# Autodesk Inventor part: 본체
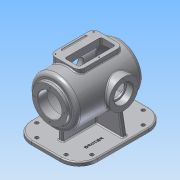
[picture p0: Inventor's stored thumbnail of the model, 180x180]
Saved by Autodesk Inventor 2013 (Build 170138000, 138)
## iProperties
Created: 2016-02
Part Number: 본체
Material: 알루미늄 6061
Document SubType Name: Modeling
Designer: mduedu
Density: 2.71 g/cm^3
Mass: 4129.67 g
Surface Area: 2907.55 cm^2
Volume: 1523.86 cm^3
Author: mduedu
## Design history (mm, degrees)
sketch "스케치2"
  geometry: L1 (0, 100)-(0, -100); L2 (65, -75.993)-(65, 100); L3 (65, 100)-(0, 100); A1 r 100 centre (0, 0) between (0, -100) and (65, -75.993); 2 further points
  constraints: 6 end point, 2 midpoint, 2 point on circle, 1 centre point, 1 coincident, 1 horizontal, 1 parallel, 1 vertical
  dimensions: "d3" = 200 distance of L1.start L1.end; "d5" = 130 diameter of L2 L1; "d6" = 100 radius of A1
revolve "회전1" sketch "스케치2" stored, may be unused: angle "d7" = 90 deg
sketch "스케치3"
  geometry: C1 r 47.5 at (0, 0); 1 further point
  constraints: 1 centre point, 1 coincident
  dimensions: "d8" = 95 diameter of C1
extrude "돌출2" join sketch "스케치3" distance "d10" = 10; taper "d11" = 0 deg
sketch "스케치5"
  geometry: L1 (47.5, 110)-(47.5, 100) reference; L2 (47.5, 100)-(65, 100) reference; L3 (65, 100)-(65, -75.993) reference; L4 (-65, -75.993)-(-65, 100) reference; L5 (-65, 100)-(-47.5, 100) reference; L6 (-47.5, 100)-(-47.5, 110) reference; L7 (-47.5, 110)-(47.5, 110) reference; L8 (55, 85)-(55, -71.239); L9 (0, 85)-(55, 85); L10 (0, 85)-(0, -90); A1 r 100 centre (0, 0) between (0, -100) and (65, -75.993) reference; A2 r 100 centre (0, 0) between (-65, -75.993) and (0, -100) reference; A3 r 90 centre (0, 0) between (0, -90) and (55, -71.239); 1 further point
  constraints: 6 end point, 2 point on circle, 1 centre point, 1 parallel, 1 perpendicular, 1 point on line, 1 vertical
  dimensions: "d13" = 10 distance between parallel lines of L3 L8; "d14" = 10 radial gap between concentric circles of A3 A1; "d15" = 15 distance between parallel lines of L9 L2
revolve "회전2" sketch "스케치5" stored, may be unused: angle "d16" = 90 deg
hole "구멍1" diameter "d19" = 65; stored, may be unused: countersink angle "d23" = 90 deg, drill point angle "d25" = 118 deg; dims "d17" = 10, "d18" = 10, "d20" = 6, "d21" = 4, "d22" = 2, "d24" = 8
node "작업 평면1"
sketch "스케치6"
  geometry: L1 (47.5, 110)-(-47.5, 110) reference; C1 r 40 at (0, -17); 1 further point
  constraints: 1 centre point, 1 vertical alignment
  dimensions: "d27" = 80 diameter of C1; "d29" = 127 distance from line of C1.centre L1
extrude "돌출3" join sketch "스케치6" stored distance "d30" = 10; taper "d31" = 0 deg
hole "구멍2" diameter "d34" = 42; stored, may be unused: countersink angle "d38" = 90 deg, drill point angle "d40" = 118 deg; dims "d32" = 10, "d33" = 10, "d35" = 6, "d36" = 52, "d37" = 18, "d39" = 8
sketch "스케치7" dims "d41" = 65
  geometry: C1 r 40 at (0, 0) reference; 3 further points
  constraints: 2 vertical alignment, 1 coincident, 2 other
hole "구멍3" sketch "스케치7" at (0, 32.5) diameter "d43" = 3.242; stored, may be unused: countersink angle "d47" = 90 deg, drill point angle "d49" = 118 deg; dims "d44" = 11, "d45" = 13, "d46" = 18, "d48" = 13
sketch "스케치8" dims "d53" = 80
  geometry: 3 further points
  constraints: 2 vertical alignment, 1 coincident, 2 other
hole "구멍4" sketch "스케치8" at (0, 40) diameter "d56" = 3.242; stored, may be unused: countersink angle "d60" = 90 deg, drill point angle "d62" = 118 deg; dims "d57" = 11, "d58" = 13, "d59" = 18, "d61" = 13
fillet "모깎기1" dims "d66" = 10
fillet "모깎기2" dims "d67" = 3
fillet "모깎기3" dims "d68" = 0.3
chamfer "모따기1" distance "d69" = 1; stored, may be unused: second distance "d70" = 2, angle "d71" = 45 deg
node "작업 평면5"
sketch "스케치23"
  geometry: L1 (6, 80)-(-6, 80); L2 (-6, 80)-(-6, -60); L3 (-6, -60)-(6, -60); L4 (6, -60)-(6, 80); L5 (-55, 100)-(55, 100) reference; 2 further points
  constraints: 8 end point, 2 parallel, 1 horizontal, 1 midpoint, 1 perpendicular, 1 vertical alignment
  dimensions: "d177" = 12 distance of L1.start L1.end; "d179" = 140 distance of L3.end L1.start; "d180" = 20 distance between parallel lines of L1 L5
extrude "돌출14" join sketch "스케치23" stored distance "d181" = 10; taper "d182" = 0 deg
node "작업 평면6"
sketch "스케치15"
  geometry: L1 (-30, 60)-(50, 60); L2 (50, 60)-(50, -60); L3 (50, -60)-(-30, -60); L4 (-30, -60)-(-30, 60); 3 further points
  constraints: 8 end point, 2 parallel, 1 horizontal, 1 horizontal alignment, 1 midpoint, 1 perpendicular, 1 vertical alignment
  dimensions: "d110" = 80 distance of L2.end L3.end; "d112" = 60 distance from line of L3 point (10, 0); "d113" = 120 distance of L1.end L2.end; "d149" = 30 distance from line of L4 point (0, 0)
extrude "돌출8" join sketch "스케치15" stored distance "d114" = 10; taper "d115" = 0 deg
fillet "모깎기7" dims "d116" = 15
sketch "스케치16"
  geometry: L1 (-30, -45)-(-30, 45) reference; L2 (-15, 60)-(35, 60) reference; L3 (35, -60)-(-15, -60) reference; L4 (-20, -45)-(-20, 45); L5 (-15, 50)-(15, 50); L6 (20, 45)-(20, -45); L7 (15, -50)-(-15, -50); L8 (50, 45)-(50, -45) reference; A1 r 15 centre (-15, -45) between (-30, -45) and (-15, -60) reference; A2 r 15 centre (-15, 45) between (-15, 60) and (-30, 45) reference; A3 r 5 centre (-15, -45) between (-20, -45) and (-15, -50); A4 r 5 centre (-15, 45) between (-15, 50) and (-20, 45); A5 r 5 centre (15, 45) between (20, 45) and (15, 50); A6 r 5 centre (15, -45) between (15, -50) and (20, -45); A7 r 15 centre (35, 45) between (50, 45) and (35, 60) reference; A8 r 15 centre (35, -45) between (35, -60) and (50, -45) reference
  constraints: 8 end point, 8 point on circle, 4 centre point, 2 equal radius, 3 other
  dimensions: "d137" = 10 distance between parallel lines of L4 L1; "d150" = 40 distance between parallel lines of L6 L4; "d151" = 100 distance between parallel lines of L7 L5
extrude "돌출9" cut sketch "스케치16" stored distance "d118" = 10; taper "d119" = 0 deg
fillet "모깎기8" dims "d120" = 3
sketch "스케치17"
  geometry: L1 (-30, -45)-(-30, 45) reference; L2 (-20, 45)-(-20, -45) reference; L3 (-15, -50)-(15, -50) reference; L4 (20, -45)-(20, 45) reference; L5 (15, 50)-(-15, 50) reference; L6 (-15, 60)-(35, 60) reference; L7 (35, -60)-(-15, -60) reference; L8 (15, 55)-(-15, 55); L9 (-25, 45)-(-25, -45); L10 (-15, -55)-(15, -55); L11 (25, -45)-(25, 45); L12 (50, 45)-(50, -45) reference; L13 (35, 55)-(-15, 55); L14 (-25, 45)-(-25, -45); L15 (-15, -55)-(35, -55); L16 (45, -45)-(45, 45); A1 r 5 centre (-15, 45) between (-15, 50) and (-20, 45) reference; A2 r 5 centre (-15, -45) between (-20, -45) and (-15, -50) reference; A3 r 5 centre (15, -45) between (15, -50) and (20, -45) reference; A4 r 5 centre (15, 45) between (20, 45) and (15, 50) reference; A5 r 15 centre (-15, 45) between (-15, 60) and (-30, 45) reference; A6 r 15 centre (-15, -45) between (-30, -45) and (-15, -60) reference; A7 r 10 centre (-15, 45) between (-15, 55) and (-25, 45); A8 r 10 centre (-15, -45) between (-25, -45) and (-15, -55); A9 r 10 centre (15, -45) between (15, -55) and (25, -45); A10 r 10 centre (15, 45) between (25, 45) and (15, 55); A11 r 15 centre (35, 45) between (50, 45) and (35, 60) reference; A12 r 15 centre (35, -45) between (35, -60) and (50, -45) reference; A13 r 10 centre (-15, 45) between (-15, 55) and (-25, 45); A14 r 10 centre (-15, -45) between (-25, -45) and (-15, -55); A15 r 10 centre (35, -45) between (35, -55) and (45, -45); A16 r 10 centre (35, 45) between (45, 45) and (35, 55); 6 further points
  constraints: 18 point on circle, 16 end point, 8 centre point, 4 midpoint, 4 tangent, 11 other
  dimensions: "d138" = 5 distance between parallel lines of L8 L6; "d157" = 5 distance between parallel lines of L12 L16
hole "구멍5" sketch "스케치17" at (-25, 0), (42.071, 52.071), (42.071, -52.071) diameter "d122" = 3.242; stored, may be unused: countersink angle "d126" = 90 deg, drill point angle "d128" = 118 deg; dims "d123" = 9, "d124" = 13, "d125" = 18, "d127" = 11
sketch "스케치19"
  geometry: L1 (-50, 70)-(-35, 70) reference; L2 (-50, 42.603)-(-50, 70) reference; C1 r 2.5 at (-43, 70); 1 further point
  constraints: 1 centre point, 1 point on line
  dimensions: "d152" = 5 diameter of C1; "d153" = 7 distance from line of C1.centre L2
extrude "돌출11" cut sketch "스케치19" stored distance "d154" = 70; taper "d155" = 0 deg
fillet "모깎기11" dims "d156" = 2.5
sketch "스케치20"
  geometry: L1 (-90, 120)-(90, 120); L2 (90, 120)-(90, -120); L3 (90, -120)-(-90, -120); L4 (-90, -120)-(-90, 120); 3 further points
  constraints: 8 end point, 2 parallel, 2 vertical alignment, 1 coincident, 1 horizontal, 1 midpoint, 1 perpendicular
  dimensions: "d162" = 180 distance of L1.start L1.end; "d164" = 240 distance of L1.end L2.end; "d165" = 120 distance from line of L1 point (0, 0)
extrude "돌출12" join sketch "스케치20" distance "d166" = 10; taper "d167" = 0 deg
fillet "모깎기12" dims "d168" = 50
node "작업 평면8"
  node "작업축1"
sketch "스케치24"
  geometry: L1 (128, 34.121)-(127.026, 32.5) reference; L2 (127.026, 32.5)-(128, 30.879) reference; L3 (128, 30.879)-(141, 30.879) reference; L4 (141, 30.879)-(141, 27) reference; L5 (141, 27)-(140, 26) reference; L6 (140, 26)-(123.3, 26) reference; L7 (123, 25.7)-(123, 21) reference; L8 (123, 21)-(116.833, 21) reference; L9 (86, 51.235)-(86, 70) reference; L10 (86, 70)-(106.5, 70) reference; L11 (111.5, 70)-(116, 70) reference; L12 (116, 70)-(116, 42.603) reference; L13 (118.678, 40)-(141, 40) reference; L14 (141, 40)-(141, 34.121) reference; L15 (141, 34.121)-(128, 34.121) reference; L16 (4, -34.121)-(4.974, -32.5) reference; L17 (4.974, -32.5)-(4, -30.879) reference; L18 (4, -30.879)-(-9, -30.879) reference; L19 (-9, -30.879)-(-9, -27) reference; L20 (-9, -27)-(-8, -26) reference; L21 (-8, -26)-(8.7, -26) reference; L22 (9, -25.7)-(9, -21) reference; L23 (9, -21)-(15.167, -21) reference; L24 (116.833, -21)-(123, -21) reference; L25 (123, -21)-(123, -25.7) reference; L26 (123.3, -26)-(140, -26) reference; L27 (140, -26)-(141, -27) reference; L28 (141, -27)-(141, -30.879) reference; L29 (141, -30.879)-(128, -30.879) reference; L30 (128, -30.879)-(127.026, -32.5) reference; L31 (127.026, -32.5)-(128, -34.121) reference; L32 (128, -34.121)-(141, -34.121) reference; L33 (141, -34.121)-(141, -40) reference; L34 (141, -40)-(118.678, -40) reference; L35 (72, -64.722)-(72, -100) reference; L36 (72, -100)-(156, -100) reference; L37 (156, -100)-(156, -110) reference; L38 (156, -110)-(-24, -110) reference; L39 (-24, -110)-(-24, -100) reference; L40 (-24, -100)-(60, -100) reference; L41 (60, -100)-(60, -64.722) reference; L42 (13.322, -40)-(-9, -40) reference; L43 (-9, -40)-(-9, -34.121) reference; L44 (-9, -34.121)-(4, -34.121) reference; L45 (4.974, 32.5)-(4, 34.121) reference; L46 (4, 34.121)-(-9, 34.121) reference; L47 (-9, 34.121)-(-9, 40) reference; L48 (-9, 40)-(13.322, 40) reference; L49 (36, 59.456)-(36, 70) reference; L50 (36, 70)-(46, 70) reference; L51 (46, 70)-(46, 51.235) reference; L52 (15.167, 21)-(9, 21) reference; L53 (9, 21)-(9, 25.7) reference; L54 (8.7, 26)-(-8, 26) reference; L55 (-8, 26)-(-9, 27) reference; L56 (-9, 27)-(-9, 30.879) reference; L57 (-9, 30.879)-(4, 30.879) reference; L58 (4, 30.879)-(4.974, 32.5) reference; L59 (-1, -40)-(-11.58, -100); A1 r 0.3 centre (123.3, 25.7) between (123.3, 26) and (123, 25.7) reference; A2 r 55 centre (66, 0) between (116.833, 21) and (86, 51.235) reference; A3 r 2.5 centre (109, 70) between (106.5, 70) and (111.5, 70) reference; A4 r 3 centre (119, 42.603) between (116, 42.603) and (116.516, 40.92) reference; A5 r 0.3 centre (8.7, -25.7) between (8.7, -26) and (9, -25.7) reference; A6 r 55 centre (66, 0) between (15.167, -21) and (116.833, -21) reference; A7 r 0.3 centre (123.3, -25.7) between (123, -25.7) and (123.3, -26) reference; A8 r 65 centre (66, 0) between (72, -64.722) and (116.354, -41.103) reference; A9 r 65 centre (66, 0) between (15.646, -41.103) and (60, -64.722) reference; A10 r 65 centre (66, 0) between (34.456, 56.833) and (15.646, 41.103) reference; A11 r 3 centre (33, 59.456) between (34.456, 56.833) and (36, 59.456) reference; A12 r 55 centre (66, 0) between (46, 51.235) and (15.167, 21) reference; A13 r 0.3 centre (8.7, 25.7) between (9, 25.7) and (8.7, 26) reference; 1 further point
  constraints: 2 end point, 2 point on line, 4 other
  dimensions: "d184" = 8 distance of L59.start L42.end; "d185" = 100 deg angle of L59 L40
feature "리브2" sketch "스케치24" dims "d186" = 1, "d187" = 12, "d188" = 0, "d189" = 0, "d190" = 1, "d191" = 1
fillet "모깎기15" dims "d192" = 3
fillet "모깎기16" dims "d193" = 3
sketch "스케치25"
  geometry: L1 (90, -70)-(90, 70) reference; L2 (40, 120)-(-40, 120) reference; L3 (-90, 70)-(-90, -70) reference; L4 (-40, -120)-(40, -120) reference; L5 (-74.004, 8)-(-9, 8) reference; L6 (-80.097, 20)-(-80.097, 14) reference; L7 (-9, 26)-(-74.004, 26) reference; L8 (-9, 57)-(-9, 26) reference; L9 (3, 63)-(-3, 63) reference; L10 (9, 26)-(9, 57) reference; L11 (74.004, 26)-(9, 26) reference; L12 (80.097, 14)-(80.097, 20) reference; L13 (9, 8)-(74.004, 8) reference; L14 (9, -77)-(9, 8) reference; L15 (-3, -83)-(3, -83) reference; L16 (-9, 8)-(-9, -77) reference; L17 (-40, 105)-(40, 105); L18 (75, 70)-(75, -70); L19 (40, -105)-(-40, -105); L20 (-75, -70)-(-75, 70); C1 r 5 at (-75, 70); C2 r 5 at (-40, 105); C3 r 5 at (40, 105); C4 r 5 at (75, 70); C5 r 5 at (75, -70); C6 r 5 at (40, -105); C7 r 5 at (-40, -105); C8 r 5 at (-75, -70); A1 r 50 centre (40, 70) between (90, 70) and (40, 120) reference; A2 r 50 centre (-40, 70) between (-40, 120) and (-90, 70) reference; A3 r 50 centre (-40, -70) between (-90, -70) and (-40, -120) reference; A4 r 50 centre (40, -70) between (40, -120) and (90, -70) reference; A5 r 6 centre (-3, 57) between (-3, 63) and (-9, 57) reference; A6 r 6 centre (3, 57) between (9, 57) and (3, 63) reference; A7 r 6 centre (3, -77) between (3, -83) and (9, -77) reference; A8 r 6 centre (-3, -77) between (-9, -77) and (-3, -83) reference; A9 r 35 centre (40, 70) between (75, 70) and (40, 105); A10 r 35 centre (40, -70) between (40, -105) and (75, -70); A11 r 35 centre (-40, -70) between (-75, -70) and (-40, -105); A12 r 35 centre (-40, 70) between (-40, 105) and (-75, 70); 5 further points; 4 other entities
  constraints: 12 centre point, 8 coincident, 8 end point, 8 point on circle, 7 equal radius, 11 other
  dimensions: "d194" = 15 distance between parallel lines of L17 L2; "d195" = 10 diameter of C1
extrude "돌출15" cut sketch "스케치25" stored distance "d197" = 10; taper "d198" = 0 deg
fillet "모깎기14" dims "d170" = 3
sketch "스케치22"
  geometry: L1 (90, -70)-(90, 70) reference; 2 further points
  constraints: 1 other
  dimensions: "d174" = 40 distance from line of L1 point (50, -40); "d199" = 40 vertical distance of point (50, -40) point (0, 0)
feature "엠보싱2" sketch "스케치22" dims "d13" = 10, "d175" = 0.5, "d176" = 0
node "솔리드2"
pattern_circular "원형 패턴1" dims angle "d51" = 360 deg
mirror "대칭1"
pattern_circular "원형 패턴2" dims angle "d64" = 360 deg
mirror "대칭3"
node "투영된 루프2"
node "절단 모서리 투영1"
node "절단 모서리 투영2"
node "절단 모서리 투영3"
node "절단 모서리 투영4"
other parameters: "d26" = 75, "d183" = 0
